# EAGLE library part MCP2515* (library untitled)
MCP2515 Standalone CAN-Controller by Microchip Eagle-Lib. by MartinThomas
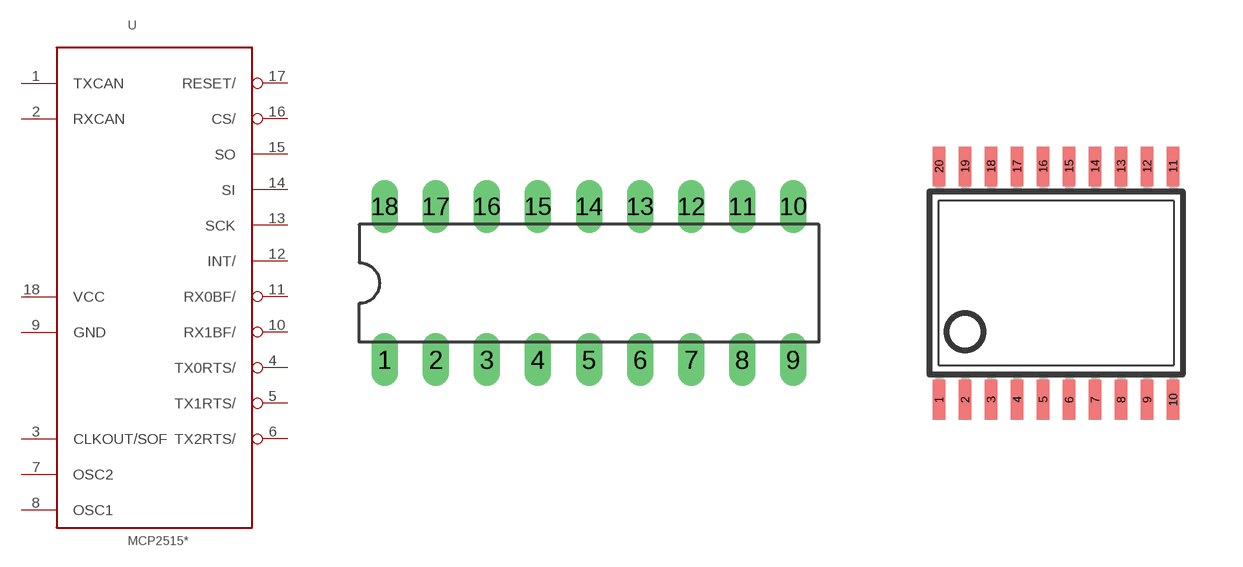
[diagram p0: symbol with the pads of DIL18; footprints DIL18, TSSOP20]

Designator prefix -

## MCP2515DIL  [DIL18]
1  TXCAN  out
2  RXCAN  in
3  CLKOUT/SOF
4  TX0RTS/
5  TX1RTS/
6  TX2RTS/
7  OSC2
8  OSC1
9  GND  sup
10  RX1BF/
11  RX0BF/
12  INT/  out
13  SCK  in
14  SI  in
15  SO  out
16  CS/  in
17  RESET/  in
18  VCC  pwr

## MCP2515TSOP  [TSSOP20]
1  TXCAN  out
2  RXCAN  in
3  CLKOUT/SOF
4  TX0RTS/
5  TX1RTS/
7  TX2RTS/
8  OSC2
9  OSC1
10  GND  sup
11  RX1BF/
12  RX0BF/
13  INT/  out
14  SCK  in
16  SI  in
17  SO  out
18  CS/  in
19  RESET/  in
20  VCC  pwr

## MCP2515SO  [SO18L]
Pads as for DIL18

## Footprint DIL18 (pad centres in mm)
Dual In Line Package
drill 0.813 long: 1 -10.16,-3.81; 2 -7.62,-3.81; 3 -5.08,-3.81; 4 -2.54,-3.81; 5 0,-3.81; 6 2.54,-3.81; 7 5.08,-3.81; 8 7.62,-3.81; 9 10.16,-3.81; 10 10.16,3.81; 11 7.62,3.81; 12 5.08,3.81; 13 2.54,3.81; 14 0,3.81; 15 -2.54,3.81; 16 -5.08,3.81; 17 -7.62,3.81; 18 -10.16,3.81

## Footprint TSSOP20 (pad centres in mm)
Thin Shrink Small Outline Plastic 20 MAX3223-MAX3243.pdf
smd 0.305 x 0.991: 1 -2.925,-2.918; 2 -2.275,-2.918; 3 -1.625,-2.918; 4 -0.975,-2.918; 5 -0.325,-2.918; 6 0.325,-2.918; 7 0.975,-2.918; 8 1.625,-2.918; 9 2.275,-2.918; 10 2.925,-2.918; 11 2.925,2.918; 12 2.275,2.918; 13 1.625,2.918; 14 0.975,2.918; 15 0.325,2.918; 16 -0.325,2.918; 17 -0.975,2.918; 18 -1.625,2.918; 19 -2.275,2.918; 20 -2.925,2.918

## Footprint SO18L (pad centres in mm)
Small Outline Package
smd 0.66 x 2.032: 1 -5.08,-4.902; 2 -3.81,-4.902; 3 -2.54,-4.902; 4 -1.27,-4.902; 5 0,-4.902; 6 1.27,-4.902; 7 2.54,-4.902; 8 3.81,-4.902; 9 5.08,-4.902; 10 5.08,4.902; 11 3.81,4.902; 12 2.54,4.902; 13 1.27,4.902; 14 0,4.902; 15 -1.27,4.902; 16 -2.54,4.902; 17 -3.81,4.902; 18 -5.08,4.902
